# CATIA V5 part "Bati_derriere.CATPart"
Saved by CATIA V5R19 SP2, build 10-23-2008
Part number: Bati_derriere
Bounding box of the stored display mesh (mm): x 0 to 126, y -100 to 100, z 0 to 370
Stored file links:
  C:\Users\Romain\Documents\IFMA\2A\cours\S3\Projet CFAO-IAO\IAO\Catia\Bati\Bati_derriere.CATPart
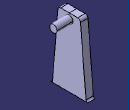
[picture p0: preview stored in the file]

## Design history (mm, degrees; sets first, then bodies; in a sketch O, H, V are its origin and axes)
Body1 (main body)
  Sketch1 on yz-plane, origin (0, 0, 0), H (0, 1, 0), V (0, 0, 1)
    line L1 (0, 0) -> (100, 0)
    point P1 (100, 0)
    arc A1 centre (100, 9.4968) radius 9.4968 from (90.537, 8.697) to (100, 0) ccw
    point P3 (90.537, 8.697)
    line L2 (90.537, 8.697) -> (60, 370)
    point P4 (60, 370)
    line L3 (60, 370) -> (0, 370)
    point P5 (0, 370)
    point P6 (-100, 0)
    point P8 (-90.537, 8.697)
    point P9 (-60, 370)
    point P10 (0, 370)
    point P11 (0, 0)
    line L4 (0, 0) -> (-100, 0)
    arc A2 centre (-100, 9.4968) radius 9.4968 from (-90.537, 8.697) to (-100, 0) cw
    line L5 (-90.537, 8.697) -> (-60, 370)
    line L6 (-60, 370) -> (0, 370)
    length L1 = 100
    distance L3 L1 = 370
    length L3 = 60
    horizontal: L1 H, L3 H
    tangency: A1 L1, A1 L2
    coincidence: P5 V, O P11, P5 P10
    symmetry: P1 P6 V, P3 P8 V, P4 P9 V, P5 P10 V, O P11 V, L1 L4 V, A1 A2 V, L2 L5 V, L3 L6 V
  Pad1: profile Sketch1, direction (1, 0, 0), length 40
  Fillet1: radius 15, on edge [face of Pad1 from Sketch1.L3 | face of Pad1 from Sketch1.L2]; edge [face of Pad1 from Sketch1.L5 | face of Pad1 from Sketch1.L6]
  Sketch2 on end face of Pad1, origin (40, 0, 0), H (0, 1, 0), V (0, 0, 1)
    circle A1 centre (0, 340) radius 20
    point P1 (0, 340)
    reference projected line E1 (-100, 0) -> (0, 0) from edge [face of Pad1 from Sketch1.L4 | end face of Pad1]
    radius A1 = 20 {= 20mm}
    distance P1 E1 = 340
    coincidence: P1 V
  Pad2: profile Sketch2, direction (1, 0, 0), length 86 {= 50mm+36mm}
